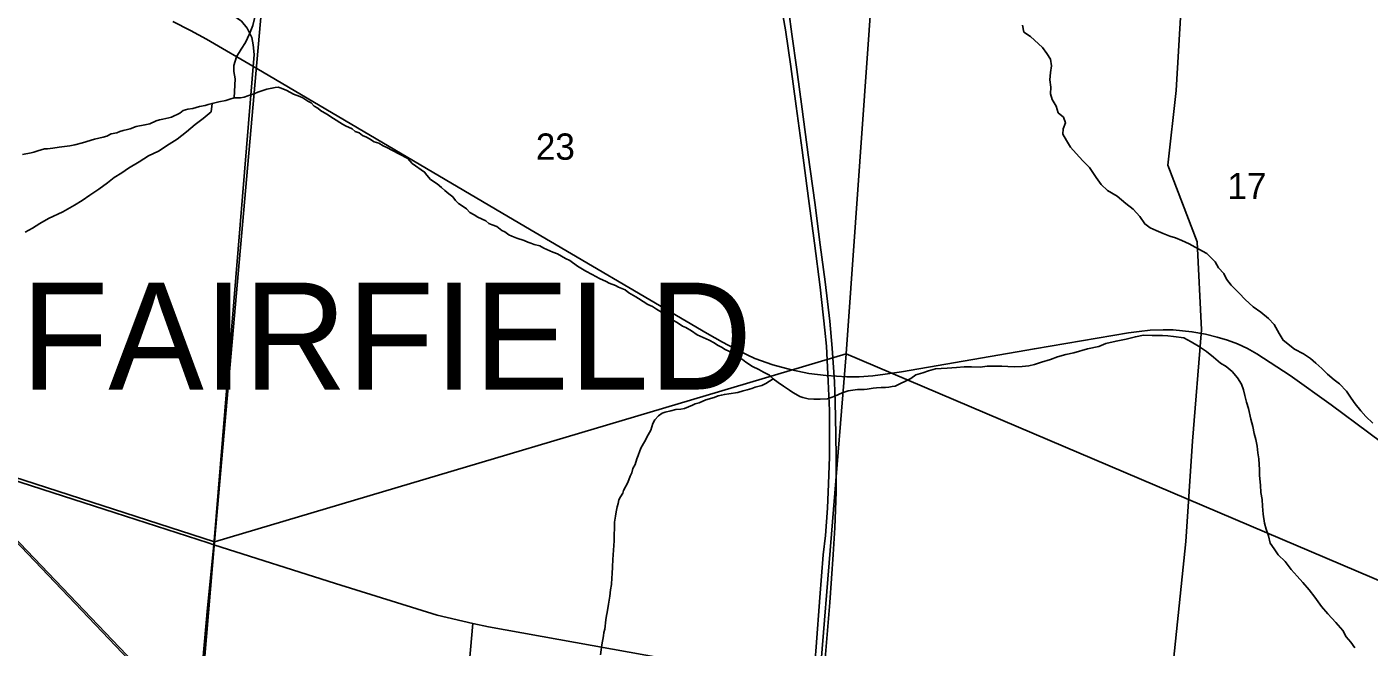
# Model space of a CAD drawing. Extents: x 0 to 34, y 0 to 22.
# Drawn here: x 11.83 to 13.969, y 17.99 to 18.979 of the extents above; entities that cross this region are included whole.
import ezdxf

# ---------------------------------------------------------------- set-up
doc = ezdxf.new("R2010")
doc.units = 0
for name, color, linetype in [('GM_X_City_Street', 7, 'Continuous'), ('GM_X_County_Road', 7, 'Continuous'), ('GM_X_Minor_River', 7, 'Continuous'), ('GM_X_Rail_Line', 7, 'Continuous'), ('GM_X_Section', 7, 'Continuous'), ('GM_X_Section_Text', 7, 'Continuous'), ('GM_X_State_Route', 7, 'Continuous'), ('GM_X_Township_Road', 7, 'Continuous'), ('GM_X_Township_Text', 7, 'Continuous')]:
    doc.layers.add(name, color=color, linetype=linetype)

msp = doc.modelspace()

# ---------------------------------------------------------------- linework, layer by layer
at = {"layer": 'GM_X_City_Street'}
msp.add_lwpolyline([(13.4083, 16.1778), (13.4741, 16.4074), (13.5037, 16.5097), (13.5708, 16.7457), (13.5867, 16.7949), (13.6069, 17.1775), (13.607, 17.1801), (13.6074, 17.1864), (13.6362, 17.6944), (13.6515, 17.9124), (13.6768, 18.1582), (13.6876, 18.3179), (13.702, 18.4958), (13.6948, 18.6356), (13.6485, 18.7581), (13.6616, 18.8772), (13.6809, 19.2003)], dxfattribs=at)
at = {"layer": 'GM_X_County_Road'}
msp.add_line((12.1188, 18.1558), (12.1282, 18.1528), dxfattribs=at)
for points in [[(11.6265, 19.1808), (11.6359, 19.1771), (11.8921, 19.07), (11.96, 19.0652), (12.0135, 19.0593), (12.1528, 19.0009), (12.1719, 18.9878), (12.1811, 18.9765), (12.1886, 18.9616), (12.1907, 18.9497), (12.1921, 18.9342)], [(11.6752, 18.2992), (11.678, 18.2983), (11.7367, 18.2795), (11.9707, 18.2037), (12.1188, 18.1558)], [(12.1282, 18.1528), (12.3217, 18.0914), (12.4841, 18.0406), (12.5407, 18.0277), (12.5658, 18.022), (12.9283, 17.9567), (12.945, 17.9538)], [(12.4221, 17.5423), (12.4417, 17.5713), (12.473, 17.6213), (12.501, 17.6845), (12.5147, 17.7338), (12.5407, 18.0277)]]:
    msp.add_lwpolyline(points, dxfattribs=at)
at = {"layer": 'GM_X_Minor_River'}
for points in [[(12.2005, 19.0191), (12.1967, 19.017), (12.1953, 19.0071), (12.1934, 18.9938), (12.19, 18.9806), (12.1847, 18.9674), (12.1786, 18.9535), (12.1718, 18.943), (12.1643, 18.9307), (12.1597, 18.9167), (12.1598, 18.9072), (12.1618, 18.8957), (12.1602, 18.8655)], [(13.975, 18.3469), (13.9636, 18.3575), (13.9558, 18.3665), (13.947, 18.3774), (13.9405, 18.3867), (13.9332, 18.3976), (13.9218, 18.4097), (13.9132, 18.416), (13.9025, 18.4251), (13.8936, 18.4338), (13.884, 18.4424), (13.8754, 18.4499), (13.8643, 18.4571), (13.85, 18.4647), (13.8322, 18.479), (13.8257, 18.4898), (13.8177, 18.5041), (13.8085, 18.5135), (13.7963, 18.5238), (13.7844, 18.5321), (13.7714, 18.5439), (13.7618, 18.5541), (13.7493, 18.567), (13.742, 18.5764), (13.7377, 18.5852), (13.7288, 18.5946), (13.7238, 18.6039), (13.7105, 18.6172), (13.6918, 18.6273), (13.6824, 18.6325), (13.6708, 18.6378), (13.6603, 18.6423), (13.6516, 18.6449), (13.6407, 18.649), (13.6298, 18.6539), (13.6201, 18.6584), (13.6115, 18.6644), (13.6035, 18.6764), (13.5928, 18.6877), (13.5813, 18.6972), (13.5676, 18.7087), (13.5519, 18.7179), (13.5423, 18.7273), (13.5343, 18.7386), (13.5237, 18.7545), (13.5126, 18.7651), (13.5023, 18.7764), (13.4931, 18.7866), (13.4866, 18.7974), (13.4808, 18.8075), (13.4814, 18.8162), (13.4851, 18.8256), (13.482, 18.8344), (13.4734, 18.8415), (13.4703, 18.8519), (13.4638, 18.8627), (13.4614, 18.8719), (13.4621, 18.8822), (13.4602, 18.894), (13.4613, 18.9058), (13.4627, 18.9164), (13.4611, 18.927), (13.4557, 18.936), (13.4488, 18.9457), (13.4295, 18.963), (13.4187, 18.9702), (13.4167, 18.9812)], [(12.4038, 18.7862), (12.3978, 18.789), (12.3907, 18.793), (12.3835, 18.7954), (12.376, 18.7998), (12.3715, 18.8026), (12.3648, 18.8054), (12.3595, 18.8094), (12.3535, 18.8118), (12.3483, 18.8157), (12.3378, 18.8206), (12.3329, 18.8234), (12.3187, 18.8325), (12.3082, 18.8392), (12.2981, 18.8452), (12.2936, 18.8487), (12.288, 18.8519), (12.2832, 18.8574), (12.2779, 18.8598), (12.2701, 18.8653), (12.2652, 18.8673), (12.255, 18.8714), (12.2445, 18.877), (12.2355, 18.8807), (12.2306, 18.8823), (12.226, 18.882), (12.2207, 18.8807), (12.2126, 18.879), (12.2076, 18.8776), (12.203, 18.8762), (12.1981, 18.8744), (12.1934, 18.8722), (12.1884, 18.8705), (12.1823, 18.8683), (12.1762, 18.8662), (12.1704, 18.8652), (12.1602, 18.8655), (12.1533, 18.8634), (12.1471, 18.8613), (12.136, 18.8589), (12.1253, 18.8565), (12.1192, 18.8547), (12.1142, 18.853), (12.1054, 18.8517), (12.0947, 18.8485), (12.0866, 18.8472), (12.079, 18.8451), (12.0739, 18.8411), (12.0608, 18.8346), (12.0562, 18.8335), (12.0466, 18.8315), (12.0413, 18.8305), (12.0359, 18.8287), (12.0259, 18.824), (12.0183, 18.8223), (12.0045, 18.8197), (11.9949, 18.8157), (11.9903, 18.8147), (11.9834, 18.8134), (11.978, 18.8116), (11.9734, 18.8094), (11.9642, 18.8078), (11.9577, 18.8045), (11.9515, 18.8028), (11.9378, 18.7997), (11.9186, 18.7937), (11.9067, 18.7906), (11.8983, 18.7889), (11.8815, 18.7867), (11.8716, 18.7854), (11.8632, 18.7841), (11.8582, 18.7839), (11.8475, 18.7807), (11.8414, 18.779), (11.8368, 18.7779), (11.823, 18.7753)], [(12.1253, 18.8565), (12.1239, 18.8431), (12.111, 18.8324), (12.0982, 18.8229), (12.0846, 18.8111), (12.0695, 18.7997), (12.0567, 18.7913), (12.04, 18.7803), (12.0239, 18.7727), (12.0088, 18.7633), (11.9918, 18.7531), (11.9813, 18.7457), (11.9693, 18.7384), (11.9588, 18.73), (11.9445, 18.7197), (11.9305, 18.7102), (11.9181, 18.7018), (11.9058, 18.6941), (11.8876, 18.6836), (11.8645, 18.6728), (11.851, 18.6648), (11.839, 18.6575), (11.8274, 18.6513)], [(13.2136, 18.4058), (13.209, 18.4055), (13.2036, 18.4041), (13.1983, 18.4039), (13.1915, 18.4037), (13.1842, 18.4031), (13.1789, 18.4025), (13.1689, 18.4008), (13.1644, 18.4006), (13.1537, 18.4005), (13.1388, 18.3982), (13.1292, 18.395), (13.1177, 18.39), (13.1062, 18.3857), (13.094, 18.3853), (13.089, 18.385), (13.0841, 18.3848), (13.0753, 18.3854), (13.0666, 18.3875), (13.0621, 18.3895), (13.0554, 18.3931), (13.0505, 18.3959), (13.0453, 18.3995), (13.0359, 18.4058), (13.0273, 18.4117), (13.0195, 18.4176), (13.0136, 18.4235), (13.0042, 18.4283), (12.9963, 18.4323), (12.9862, 18.4371), (12.9757, 18.4439), (12.9705, 18.4482), (12.9607, 18.453), (12.9533, 18.4593), (12.9431, 18.4641), (12.9371, 18.4681), (12.9308, 18.4713), (12.9255, 18.4748), (12.9173, 18.4792), (12.8985, 18.4877), (12.8891, 18.494), (12.8801, 18.4992), (12.8749, 18.5012), (12.8678, 18.5064), (12.8543, 18.5143), (12.8502, 18.5194), (12.8412, 18.5238), (12.8334, 18.5286), (12.827, 18.5329), (12.8195, 18.5361), (12.8124, 18.5409), (12.8049, 18.5453), (12.8004, 18.5484), (12.7891, 18.5544), (12.7836, 18.5591), (12.7727, 18.5636), (12.7682, 18.5664), (12.758, 18.5697), (12.7531, 18.5725), (12.7426, 18.5773), (12.731, 18.5837), (12.7208, 18.5893), (12.7077, 18.5969), (12.6954, 18.6059), (12.6883, 18.6091), (12.6759, 18.6167), (12.6684, 18.6192), (12.6537, 18.6256), (12.6473, 18.6296), (12.6383, 18.6317), (12.6334, 18.6338), (12.6285, 18.6354), (12.6224, 18.6379), (12.6111, 18.6416), (12.6028, 18.6448), (12.5983, 18.6472), (12.592, 18.6516), (12.5871, 18.654), (12.5789, 18.6603), (12.5714, 18.6631), (12.5665, 18.6652), (12.5617, 18.6695), (12.5489, 18.6751), (12.5429, 18.6787), (12.5358, 18.6827), (12.5306, 18.6885), (12.5224, 18.6941), (12.5179, 18.6969), (12.5131, 18.7019), (12.509, 18.7074), (12.5023, 18.7125), (12.496, 18.7176), (12.4908, 18.7223), (12.4841, 18.7285), (12.4732, 18.7353), (12.4673, 18.7419), (12.464, 18.7469), (12.4439, 18.7608), (12.4372, 18.7686), (12.4226, 18.7762), (12.4038, 18.7862)], [(13.6572, 18.4847), (13.6485, 18.4861), (13.6397, 18.4864), (13.6234, 18.4865), (13.6093, 18.4869), (13.5967, 18.4846), (13.5818, 18.4809), (13.5657, 18.4776), (13.5493, 18.4739), (13.5385, 18.4689), (13.5201, 18.4653), (13.4987, 18.4591), (13.4857, 18.4561), (13.4722, 18.4523), (13.4611, 18.4485), (13.4469, 18.444), (13.4358, 18.4401), (13.4266, 18.4381), (13.4159, 18.4369), (13.4041, 18.4365), (13.3935, 18.4369), (13.3836, 18.4376), (13.3707, 18.4376), (13.3604, 18.4375), (13.349, 18.4363), (13.3353, 18.4364), (13.3235, 18.4364), (13.3113, 18.4356), (13.2969, 18.4345), (13.287, 18.434), (13.2778, 18.4332), (13.2667, 18.4301), (13.2579, 18.427), (13.2468, 18.4239), (13.2386, 18.4178), (13.2136, 18.4058)], [(13.9462, 17.9885), (13.94, 17.9975), (13.9327, 18.0064), (13.9269, 18.0165), (13.9159, 18.029), (13.9034, 18.0427), (13.8934, 18.0548), (13.8828, 18.0692), (13.8737, 18.0809), (13.8634, 18.093), (13.8542, 18.1031), (13.8446, 18.1137), (13.8351, 18.1261), (13.824, 18.1367), (13.8178, 18.1464), (13.8113, 18.1554), (13.8086, 18.1672), (13.8051, 18.1776), (13.8023, 18.1872), (13.8001, 18.2017), (13.7993, 18.2143), (13.7985, 18.2249), (13.7966, 18.2364), (13.7957, 18.2478), (13.7943, 18.2635), (13.7942, 18.2726), (13.7932, 18.2897), (13.7916, 18.2996), (13.7904, 18.3099), (13.7884, 18.3207), (13.786, 18.3302), (13.7837, 18.3413), (13.7806, 18.3532), (13.7769, 18.3704), (13.7738, 18.3804), (13.7711, 18.3907), (13.7687, 18.3999), (13.7655, 18.4092), (13.7594, 18.4192), (13.7509, 18.429), (13.7413, 18.4369), (13.7323, 18.4425), (13.7208, 18.452), (13.71, 18.461), (13.697, 18.4694), (13.6854, 18.4762), (13.6738, 18.4827), (13.6572, 18.4847)], [(13.0195, 18.4176), (13.0079, 18.4099), (13.0013, 18.4071), (12.9906, 18.4043), (12.9856, 18.4021), (12.9779, 18.3997), (12.9718, 18.3983), (12.963, 18.3959), (12.9485, 18.3936), (12.9416, 18.3926), (12.937, 18.3916), (12.9317, 18.3902), (12.9255, 18.3877), (12.9121, 18.3842), (12.9017, 18.3792), (12.8952, 18.3778), (12.8906, 18.3757), (12.8782, 18.3703), (12.8721, 18.3693), (12.8641, 18.3684), (12.8561, 18.3667), (12.8473, 18.3642), (12.8423, 18.3625), (12.8365, 18.3584), (12.831, 18.3521), (12.8274, 18.3461), (12.8261, 18.3412), (12.8245, 18.3359), (12.8201, 18.3284), (12.8141, 18.3168), (12.8089, 18.3082), (12.8068, 18.3029), (12.804, 18.295), (12.8023, 18.2901), (12.7994, 18.281), (12.7958, 18.2746), (12.7941, 18.2678), (12.7917, 18.2622), (12.788, 18.252), (12.7808, 18.2396), (12.7799, 18.2351), (12.776, 18.2295), (12.7736, 18.2246), (12.7723, 18.2185), (12.7706, 18.2133), (12.7693, 18.2057), (12.7683, 18.1985), (12.7665, 18.189), (12.7658, 18.159), (12.765, 18.1442), (12.7638, 18.1297), (12.7635, 18.118), (12.7629, 18.1069), (12.7623, 18.1005), (12.7616, 18.0895), (12.7603, 18.0811), (12.7589, 18.0709), (12.757, 18.0584), (12.7547, 18.0448), (12.7539, 18.0402), (12.7529, 18.0334), (12.751, 18.0182), (12.7497, 18.0133), (12.7488, 18.0076), (12.7462, 17.9936), (12.7442, 17.9773)]]:
    msp.add_lwpolyline(points, dxfattribs=at)
at = {"layer": 'GM_X_Rail_Line'}
for points in [[(14.1489, 18.1976), (13.9084, 18.3758), (13.8433, 18.423), (13.79, 18.4574), (13.7754, 18.4657), (13.7593, 18.4732), (13.7436, 18.4789), (13.7271, 18.4839), (13.7081, 18.4887), (13.6866, 18.4926), (13.6569, 18.4953), (13.6407, 18.4956), (13.6201, 18.4949), (13.6026, 18.4931), (13.5854, 18.4906), (13.4358, 18.4653), (13.2241, 18.4288), (13.1976, 18.4249), (13.178, 18.4224), (13.1565, 18.4208), (13.1365, 18.4208), (13.1038, 18.4227), (13.0762, 18.4259), (13.0485, 18.432), (13.0189, 18.4397), (12.9901, 18.4501), (12.9647, 18.462), (12.9388, 18.4759), (12.914, 18.4896), (12.6064, 18.6702), (12.1964, 18.9122), (12.1164, 18.959), (12.0911, 18.9725), (12.0628, 18.9868)], [(13.9217, 15.9488), (13.7319, 16.148), (13.4771, 16.417), (13.2794, 16.622), (13.1749, 16.7337), (13.0113, 16.9036), (12.6435, 17.2905), (12.3238, 17.6231), (12.1005, 17.8566), (11.6806, 18.2963)], [(13.9235, 15.9505), (13.7337, 16.1497), (13.4789, 16.4187), (13.2812, 16.6237), (13.1767, 16.7354), (13.0131, 16.9053), (12.6453, 17.2922), (12.3256, 17.6248), (12.1023, 17.8583), (11.6823, 18.298)]]:
    msp.add_lwpolyline(points, dxfattribs=at)
at = {"layer": 'GM_X_Section'}
for points in [[(11.2353, 19.5105), (12.2122, 19.0964), (12.129, 18.1574), (11.148, 18.4749)], [(12.2122, 19.0964), (13.2088, 19.4896), (13.1359, 18.4571), (12.129, 18.1574)], [(13.2088, 19.4896), (14.3064, 19.001), (14.223, 17.9945), (13.1359, 18.4571)], [(11.148, 18.4749), (12.129, 18.1574), (12.0442, 17.1517), (11.0623, 17.4613)], [(12.129, 18.1574), (13.1359, 18.4571), (13.0485, 17.3859), (12.0442, 17.1517)], [(13.1359, 18.4571), (14.223, 17.9945), (14.1379, 16.9974), (13.0485, 17.3859)]]:
    msp.add_lwpolyline(points, close=True, dxfattribs=at)
at = {"layer": 'GM_X_State_Route'}
for points in [[(13.0832, 17.9297), (13.0878, 17.9901), (13.0938, 18.0688), (13.0989, 18.1367), (13.1026, 18.1676), (13.1059, 18.2114), (13.1074, 18.25), (13.1091, 18.2932), (13.1091, 18.3287), (13.1089, 18.367), (13.1072, 18.4138), (13.1042, 18.4695), (13.1019, 18.4948), (13.0944, 18.5636), (13.0854, 18.6336), (13.0757, 18.7048), (13.0654, 18.7822), (13.0561, 18.8522), (13.0475, 18.9151), (13.0389, 18.974), (13.0256, 19.0479), (13.0138, 19.1197), (13.003, 19.1967), (12.9967, 19.2446)], [(13.0946, 17.8772), (13.0958, 17.8932), (13.0983, 17.9272), (13.104, 17.9908), (13.1096, 18.0609), (13.1152, 18.1376), (13.1174, 18.1798), (13.1195, 18.2376), (13.1198, 18.2921), (13.119, 18.3289), (13.1181, 18.3806), (13.1169, 18.4126), (13.1132, 18.4665), (13.1094, 18.5096), (13.1024, 18.5721), (13.0945, 18.6312), (13.0856, 18.6985), (13.075, 18.7744), (13.0654, 18.8475), (13.0572, 18.9107), (13.0493, 18.967), (13.0397, 19.0395), (13.0332, 19.0873)]]:
    msp.add_lwpolyline(points, dxfattribs=at)
at = {"layer": 'GM_X_Township_Road'}
for p, q in [((12.1737, 18.7083), (12.1921, 18.9342)), ((12.1282, 18.1528), (12.1737, 18.7083))]:
    msp.add_line(p, q, dxfattribs=at)
msp.add_lwpolyline([(12.1291, 17.2509), (12.087, 17.2865), (12.0736, 17.3045), (12.0664, 17.3207), (12.059, 17.3419), (12.0574, 17.3584), (12.0631, 17.4391), (12.1177, 18.0522), (12.1282, 18.1528)], dxfattribs=at)

# ---------------------------------------------------------------- texts
at = {"layer": 'GM_X_Section_Text'}
for s, p in [('23', (12.6411, 18.7667)), ('17', (13.7432, 18.7039))]:
    msp.add_text(s, height=0.04186, rotation=0, dxfattribs=at).set_placement(p)
at = {"layer": 'GM_X_Township_Text'}
msp.add_text('FAIRFIELD', height=0.17045, rotation=0, dxfattribs=at).set_placement((11.8207, 18.4004))

doc.saveas('drawing.dxf')
